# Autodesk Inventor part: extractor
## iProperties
Created: 2006-04
Part Number: extractor
Document SubType Name: Modeling
Designer: Калинин
Author: Калинин
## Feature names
1. Выдавливание1 [Extrusion]
